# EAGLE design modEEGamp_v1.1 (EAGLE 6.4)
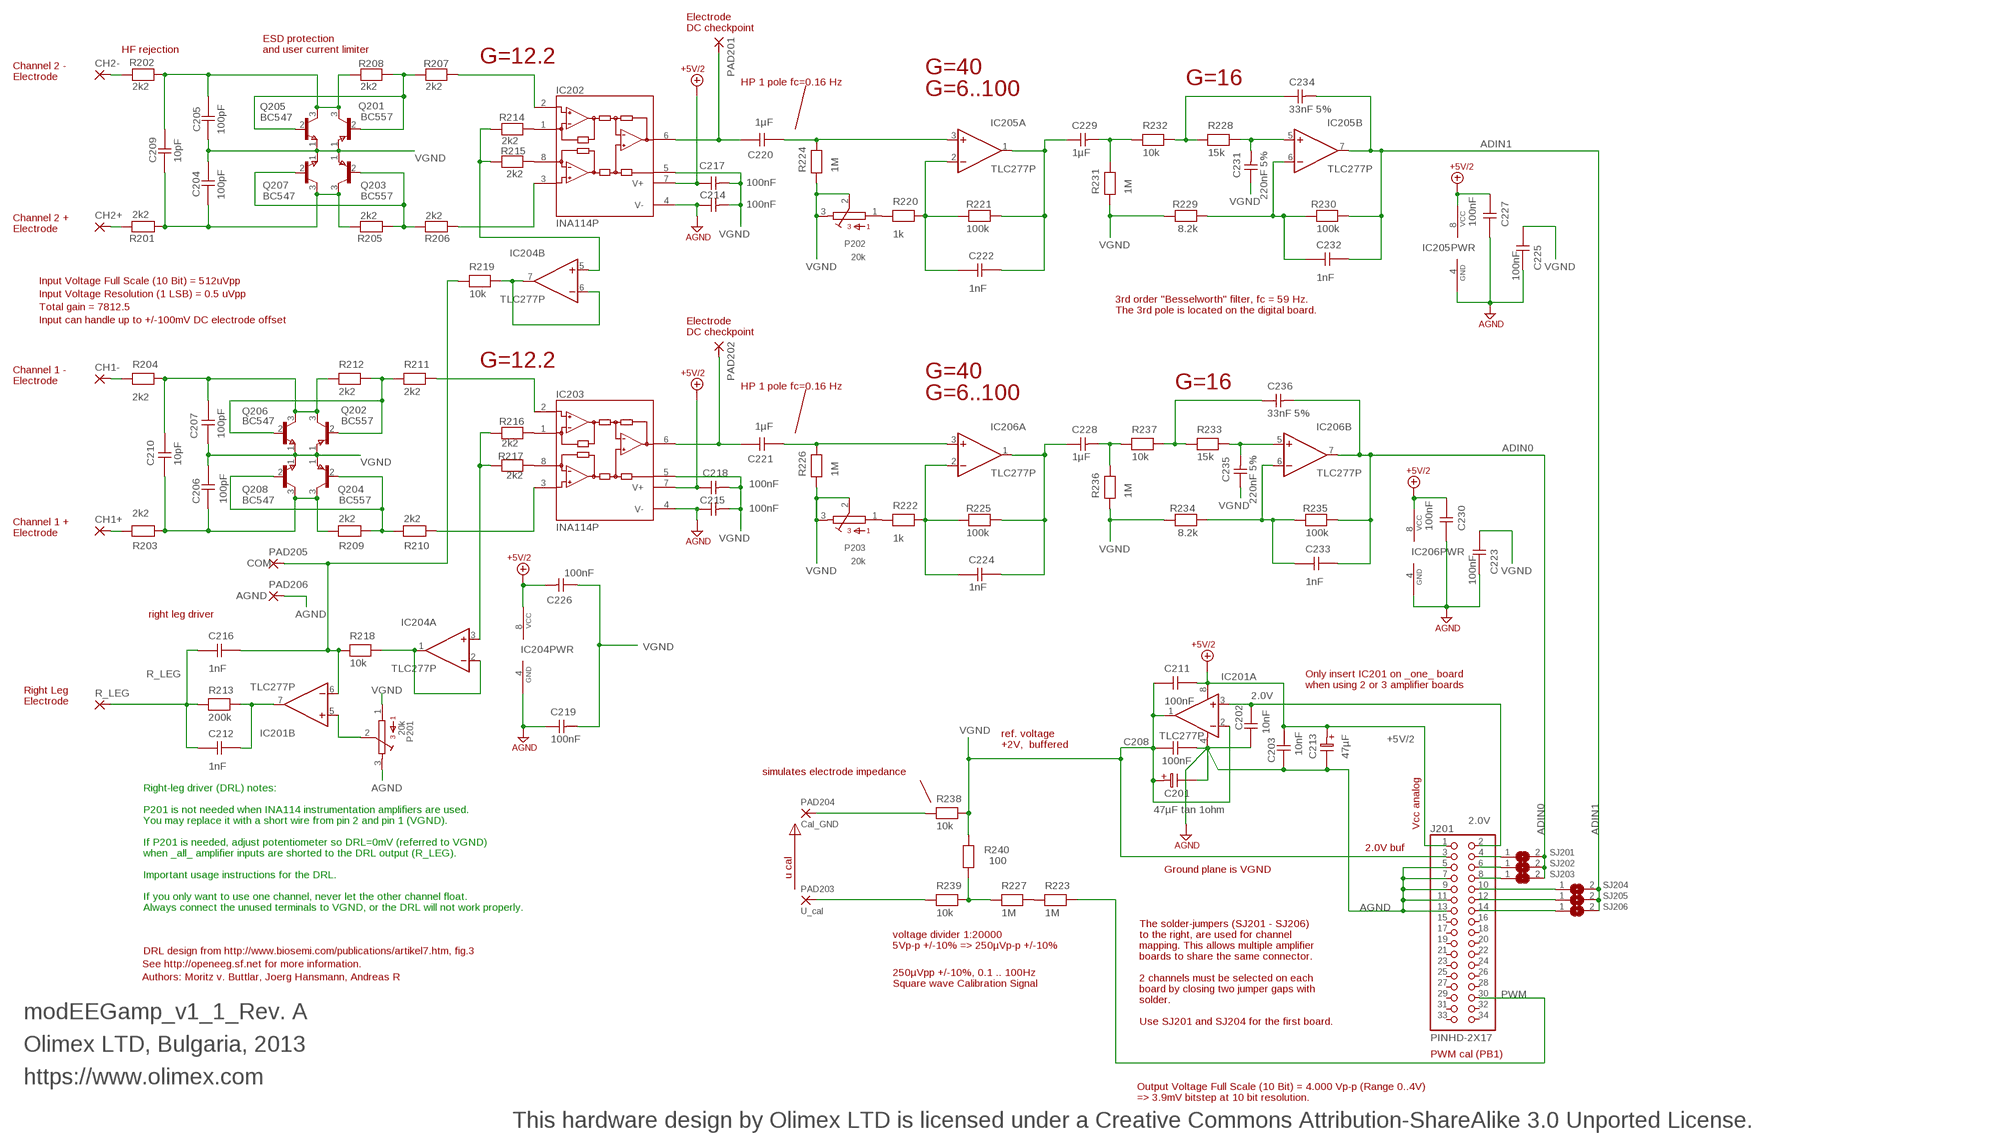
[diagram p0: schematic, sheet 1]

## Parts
C201  47µF tan 1ohm  ELC-2,5  [EL25B]
C202  10nF  CAPNP-5@2  [C-5]
C203  10nF  CAPNP-7,5  [C-5]
C204  100pF  CAPNP-7,5  [C-5]
C205  100pF  CAPNP-7,5  [C-5]
C206  100pF  CAPNP-7,5  [C-5]
C207  100pF  CAPNP-7,5  [C-5]
C208  100nF  CAPNP-7,5  [C-5]
C209  10pF  CAPNP-7,5  [C-5]
C210  10pF  CAPNP-7,5  [C-5]
C211  100nF  CAPNP-5@2  [C-5]
C212  1nF  CAPNP-7,5  [C-5]
C213  47µF  ELC-5  [EL25B]
C214  100nF  CAPNP-5  [C-5]
C215  100nF  CAPNP-5  [C-5]
C216  1nF  CAPNP-7,5  [C-5]
C217  100nF  CAPNP-5  [C-5]
C218  100nF  CAPNP-5  [C-5]
C219  100nF  CAPNP-5  [C-5]
C220  1µF  CAPNP-7,5@2  [C-10]
C221  1µF  CAPNP-7,5@2  [C-10]
C222  1nF  CAPNP-7,5  [C-5]
C223  100nF  CAPNP-5@2  [C-5]
C224  1nF  CAPNP-7,5  [C-5]
C225  100nF  CAPNP-5@2  [C-5]
C226  100nF  CAPNP-5  [C-5]
C227  100nF  CAPNP-5@2  [C-5]
C228  1µF  CAPNP-7,5@3  [C-10]
C229  1µF  CAPNP-7,5@3  [C-10]
C230  100nF  CAPNP-5@2  [C-5]
C231  220nF 5%  CAPNP-5  [C-5]
C232  1nF  CAPNP-7,5  [C-5]
C233  1nF  CAPNP-7,5  [C-5]
C234  33nF 5%  CAPNP-5  [C-5]
C235  220nF 5%  CAPNP-5  [C-5]
C236  33nF 5%  CAPNP-5  [C-5]
CH1+  1,6/0,8  [1,6/0,8]
CH1-  1,6/0,8  [1,6/0,8]
CH2+  1,6/0,8  [1,6/0,8]
CH2-  1,6/0,8  [1,6/0,8]
IC201  TLC277P  OPA2604AP  [DIL-08]
IC202  INA114P  [DIL-08]
IC203  INA114P  [DIL-08]
IC204  TLC277P  [DIL-08]
IC205  TLC277P  [DIL-08]
IC206  TLC277P  [DIL-08]
J201  PINHD-2X17  [2X17]
P201  20k  S64Y  [S64Y]
P202  20k  S64Y  [S64Y]
P203  20k  S64Y  [S64Y]
PAD201  1,6/0,8  [1,6/0,8]
PAD202  1,6/0,8  [1,6/0,8]
PAD203  U_cal  1,6/0,8  [WIREPAD1]
PAD204  Cal_GND  1,6/0,8  [WIREPAD1]
PAD205  COM  1,6/0,8  [1,6/0,8]
PAD206  AGND  1,6/0,8  [1,6/0,8]
Q201  BC557  [TO92]
Q202  BC557  [TO92]
Q203  BC557  [TO92]
Q204  BC557  [TO92]
Q205  BC547  [TO92]
Q206  BC547  [TO92]
Q207  BC547  [TO92]
Q208  BC547  [TO92]
R201  2k2  RESEU-10  [R-10]
R202  2k2  RESEU-10  [R-10]
R203  2k2  RESEU-10  [R-10]
R204  2k2  RESEU-10  [R-10]
R205  2k2  RESEU-10  [R-10]
R206  2k2  RESEU-10  [R-10]
R207  2k2  RESEU-10  [R-10]
R208  2k2  RESEU-10  [R-10]
R209  2k2  RESEU-10  [R-10]
R210  2k2  RESEU-10  [R-10]
R211  2k2  RESEU-10  [R-10]
R212  2k2  RESEU-10  [R-10]
R213  200k  RESEU-10  [R-10]
R214  2k2  RESEU-7,5  [R-10]
R215  2k2  RESEU-7,5  [R-10]
R216  2k2  RESEU-7,5  [R-10]
R217  2k2  RESEU-7,5  [R-10]
R218  10k  RESEU-10  [R-10]
R219  10k  RESEU-10@2  [R-10]
R220  1k  RESEU-7,5  [R-10]
R221  100k  RESEU-7,5  [R-10]
R222  1k  RESEU-7,5  [R-10]
R223  1M  RESEU-10@2  [R-10]
R224  1M  RESEU-7,5  [R-10]
R225  100k  RESEU-7,5  [R-10]
R226  1M  RESEU-7,5  [R-10]
R227  1M  RESEU-10@2  [R-10]
R228  15k  RESEU-7,5@2  [R-10]
R229  8.2k  RESEU-7,5  [R-10]
R230  100k  RESEU-7,5  [R-10]
R231  1M  RESEU-7,5  [R-10]
R232  10k  RESEU-7,5@2  [R-10]
R233  15k  RESEU-7,5@2  [R-10]
R234  8.2k  RESEU-7,5  [R-10]
R235  100k  RESEU-7,5  [R-10]
R236  1M  RESEU-7,5  [R-10]
R237  10k  RESEU-7,5@2  [R-10]
R238  10k  RESEU-7,5  [R-10]
R239  10k  RESEU-7,5  [R-10]
R240  100  RESEU-7,5  [R-10]
R_LEG  1,6/0,8  [1,6/0,8]
SJ201  SJ  [SJ5X5]
SJ202  SJ  [SJ5X5]
SJ203  SJ  [SJ5X5]
SJ204  SJ  [SJ5X5]
SJ205  SJ  [SJ5X5]
SJ206  SJ  [SJ5X5]

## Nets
2.0V: C202.1 IC201.3(A:+IN) J201.2
+5V/2: C203.1 C211.2 C213.1 C217.1 C218.1 C226.2 C227.2 C230.2 IC201.8(A:V+) IC202.7(V+) IC203.7(V+) IC204.8(PWR:VCC) IC205.8(PWR:VCC) IC206.8(PWR:VCC) J201.1
ADIN0: C233.2 C236.2 IC206.7(B:OUT) R235.2 SJ201.2 SJ202.2 SJ203.2
ADIN1: C232.2 C234.2 IC205.7(B:OUT) R230.2 SJ204.2 SJ205.2 SJ206.2
AGND: C201.2 C202.2 C203.2 C208.2 C213.2 C214.1 C215.1 C219.1 C223.1 C225.1 C227.1 C230.1 IC201.4(A:V-) IC202.4(V-) IC203.4(V-) IC204.4(PWR:GND) IC205.4(PWR:GND) IC206.4(PWR:GND) J201.5 J201.7 J201.9 J201.11 J201.13 P201.3 PAD206.1(P)
N$1: IC202.1(RG) R214.1
N$2: IC202.8(RG) R215.1
N$3: IC204.5(B:+IN) R214.2 R215.2
N$4: C220.2 IC202.6(OUT) PAD201.1(P)
N$5: IC202.2(-IN) R207.2
N$6: CH1-.1(P) R204.1
N$7: IC202.3(+IN) R206.2
N$8: Q201.2(B) Q205.2(B) R207.1 R208.2
N$9: C205.2 C209.2 Q201.3(C) Q205.3(C) R202.2 R208.1
N$10: Q203.2(B) Q207.2(B) R205.2 R206.1
N$11: CH1+.1(P) R203.1
N$12: IC204.3(A:+IN) R216.2 R217.2
N$13: C204.1 C209.1 Q203.3(C) Q207.3(C) R201.2 R205.1
N$14: IC203.1(RG) R216.1
N$15: CH2-.1(P) R202.1
N$16: CH2+.1(P) R201.1
N$17: C220.1 IC205.3(A:+IN) R224.2
N$18: C222.1 IC205.2(A:-IN) R220.2 R221.1
N$19: P202.1 R220.1
N$20: IC203.8(RG) R217.1
N$21: IC203.2(-IN) R211.2
N$22: C222.2 C229.1 IC205.1(A:OUT) R221.2
N$23: C229.2 R231.2 R232.1
N$24: C232.1 IC205.6(B:-IN) R229.2 R230.1
N$25: C221.2 IC203.6(OUT) PAD202.1(P)
N$26: J201.4 SJ201.1
N$27: IC203.3(+IN) R210.2
N$28: C221.1 IC206.3(A:+IN) R226.2
N$29: Q202.2(B) Q206.2(B) R211.1 R212.2
N$30: PAD204.1(P) R238.1
N$31: J201.6 SJ202.1
N$32: C207.2 C210.2 Q202.3(C) Q206.3(C) R204.2 R212.1
N$33: C212.2 IC201.7(B:OUT) R213.2
N$34: R227.1 R239.2 R240.2
N$35: J201.8 SJ203.1
N$36: J201.10 SJ204.1
N$37: J201.12 SJ205.1
N$38: C224.1 IC206.2(A:-IN) R222.2 R225.1
N$39: Q204.2(B) Q208.2(B) R209.2 R210.1
N$40: P203.1 R222.1
N$41: C216.2 IC201.6(B:-IN) PAD205.1(P) R218.1 R219.1
N$42: C224.2 C228.1 IC206.1(A:OUT) R225.2
N$43: C206.1 C210.1 Q204.3(C) Q208.3(C) R203.2 R209.1
N$44: J201.14 SJ206.1
N$45: IC204.6(B:-IN) IC204.7(B:OUT) R219.2
N$46: R223.1 R227.2
N$47: IC201.5(B:+IN) P201.2
N$48: PAD203.1(P) R239.1
N$49: C233.1 IC206.6(B:-IN) R234.2 R235.1
N$50: C228.2 R236.2 R237.1
N$51: C236.1 R233.1 R237.2
N$52: IC204.1(A:OUT) IC204.2(A:-IN) R218.2
N$53: C234.1 R228.1 R232.2
N$54: C231.2 IC205.5(B:+IN) R228.2
N$57: C235.2 IC206.5(B:+IN) R233.2
PWM: J201.30 R223.2
R_LEG: C212.1 C216.1 R213.1 R_LEG.1(P)
VGND: C201.1 C204.2 C205.1 C206.2 C207.1 C208.1 C211.1 C214.2 C215.2 C217.2 C218.2 C219.2 C223.2 C225.2 C226.1 C231.1 C235.1 IC201.1(A:OUT) IC201.2(A:-IN) IC202.5(REF) IC203.5(REF) J201.3 P201.1 P202.2 P202.3 P203.2 P203.3 Q201.1(E) Q202.1(E) Q203.1(E) Q204.1(E) Q205.1(E) Q206.1(E) Q207.1(E) Q208.1(E) R224.1 R226.1 R229.1 R231.1 R234.1 R236.1 R238.2 R240.1
Unconnected: J201.15 J201.16 J201.17 J201.18 J201.19 J201.20 J201.21 J201.22 J201.23 J201.24 J201.25 J201.26 J201.27 J201.28 J201.29 J201.31 J201.32 J201.33 J201.34

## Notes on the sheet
- Electrode
- DC checkpoint
- ESD protection
- HF rejection | and user current limiter
- G=12.2
- Channel 2 -
- G=40
- Electrode
- HP 1 pole fc=0.16 Hz | G=16
- G=6..100
- Channel 2 +
- Electrode
- Input Voltage Full Scale (10 Bit) = 512uVpp
- Input Voltage Resolution (1 LSB) = 0.5 uVpp
- 3rd order "Besselworth" filter, fc = 59 Hz.
- Total gain = 7812.5
- The 3rd pole is located on the digital board.
- Input can handle up to +/-100mV DC electrode offset | Electrode
- DC checkpoint
- G=12.2
- Channel 1 -
- G=40
- Electrode
- HP 1 pole fc=0.16 Hz | G=16
- G=6..100
- Channel 1 +
- Electrode
- right leg driver
- Only insert IC201 on _one_ board
- when using 2 or 3 amplifier boards
- Right Leg
- Electrode
- ref. voltage
- +2V,  buffered
- simulates electrode impedance
- Right-leg driver (DRL) notes:
- P201 is not needed when INA114 instrumentation amplifiers are used.
- You may replace it with a short wire from pin 2 and pin 1 (VGND).
- Vcc analog
- If P201 is needed, adjust potentiometer so DRL=0mV (referred to VGND)
- 2.0V buf
- when _all_ amplifier inputs are shorted to the DRL output (R_LEG). | u cal
- Ground plane is VGND
- Important usage instructions for the DRL.
- If you only want to use one channel, never let the other channel float.
- Always connect the unused terminals to VGND, or the DRL will not work properly.
- The solder-jumpers (SJ201 - SJ206)
- voltage divider 1:20000 | to the right, are used for channel
- 5Vp-p +/-10% => 250µVp-p +/-10% | mapping. This allows multiple amplifier
- DRL design from http://www.biosemi.com/publications/artikel7.htm, fig.3
- boards to share the same connector.
- See http://openeeg.sf.net for more information.
- 250µVpp +/-10%, 0.1 .. 100Hz
- Authors: Moritz v. Buttlar, Joerg Hansmann, Andreas R | 2 channels must be selected on each
- Square wave Calibration Signal
- board by closing two jumper gaps with
- solder.
- modEEGamp_v1_1_Rev. A
- Use SJ201 and SJ204 for the first board.
- Olimex LTD, Bulgaria, 2013
- PWM cal (PB1)
- https://www.olimex.com
- Output Voltage Full Scale (10 Bit) = 4.000 Vp-p (Range 0..4V)
- => 3.9mV bitstep at 10 bit resolution.
- This hardware design by Olimex LTD is licensed under a Creative Commons Attribution-ShareAlike 3.0 Unported License.

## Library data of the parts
C201 = DISCRETE@3:ELC-2,5
C202 C211 C223 C225 C227 C230 = DISCRETE:CAPNP-5@2
C203-C210 C212 C216 C222 C224 C232 C233 = DISCRETE:CAPNP-7,5
C213 = DISCRETE@2:ELC-5
C214 C215 C217-C219 C226 C231 C234-C236 = DISCRETE:CAPNP-5
C220 C221 = DISCRETE:CAPNP-7,5@2
C228 C229 = DISCRETE:CAPNP-7,5@3
CH1+ CH1- CH2+ CH2- PAD201 PAD202 PAD205 PAD206 R_LEG = WIREPAD:1,6/0,8: THROUGH-HOLE PAD
IC201 = BURR:OPA2604AP
IC202 IC203 = BURR:INA114P
IC204-IC206 = BURR:TLC277P
J201 = pinhead_:PINHD-2X17
P201 = TRIMPOT:S64Y
P202 P203 = TRIMPOT@2:S64Y
PAD203 PAD204 = WIREPAD@2:1,6/0,8
Q201-Q204 = pnp:BC557
Q205-Q208 = NPN:BC547
R201-R213 R218 = DISCRETE:RESEU-10
R214-R217 R220-R222 R224-R226 R229-R231 R234-R236 R238-R240 = DISCRETE:RESEU-7,5
R219 R223 R227 = DISCRETE:RESEU-10@2
R228 R232 R233 R237 = DISCRETE:RESEU-7,5@2
SJ201-SJ206 = JUMPER:SJ

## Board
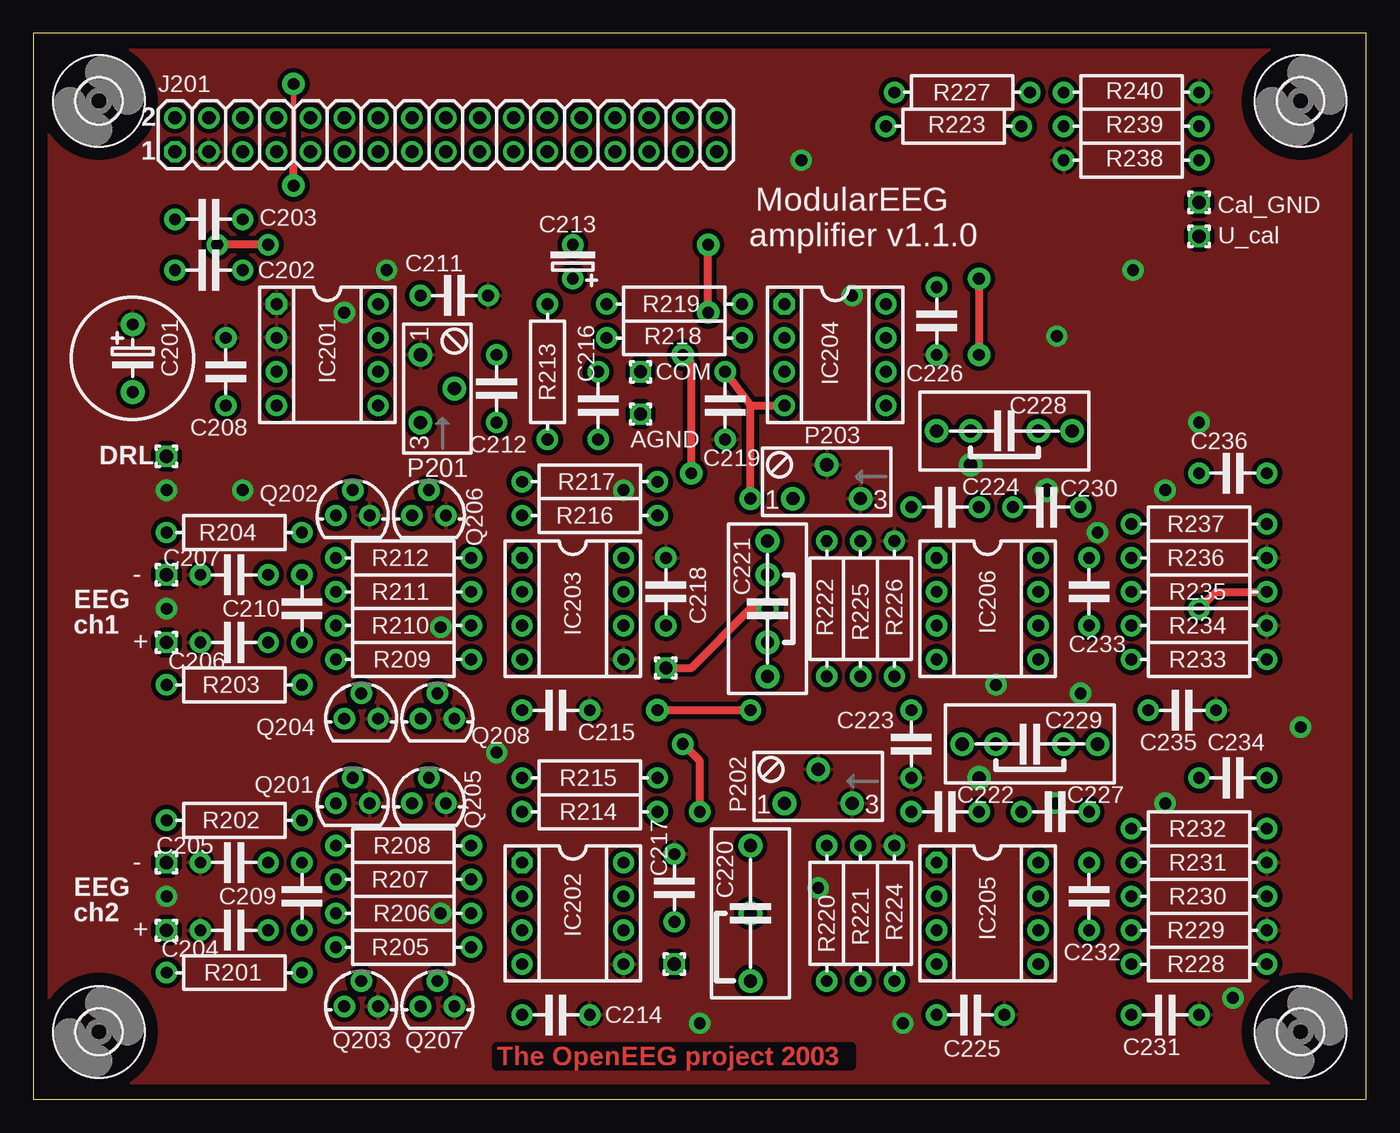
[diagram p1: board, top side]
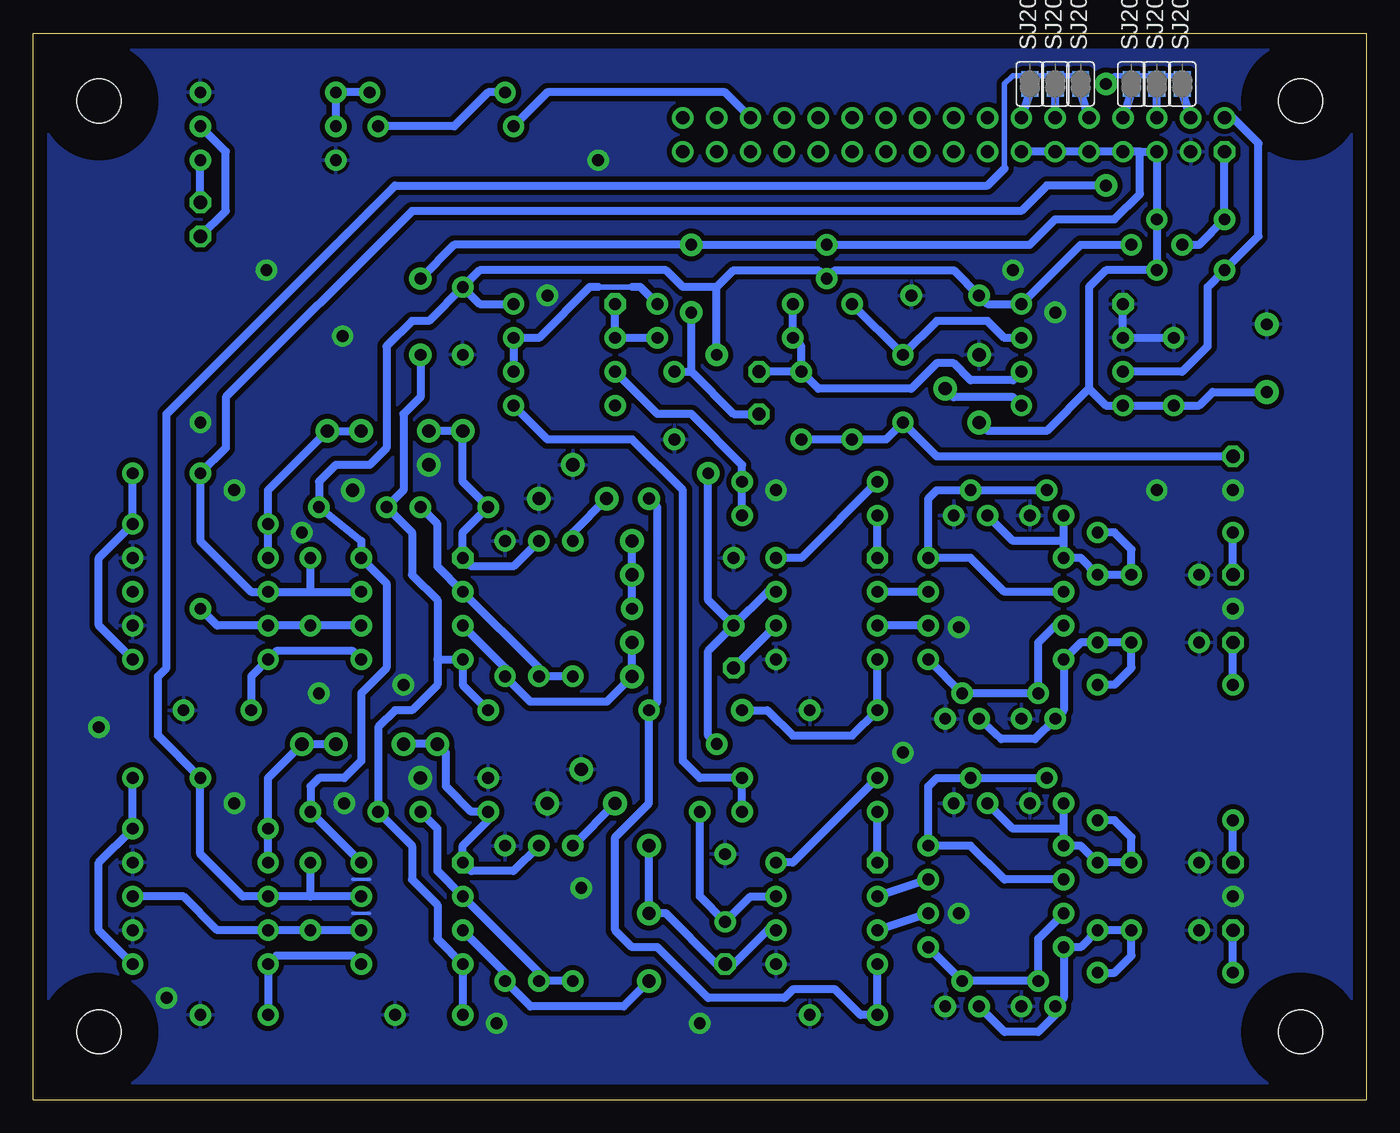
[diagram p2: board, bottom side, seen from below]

Size 100 x 80.01 mm. Coordinates in mm from the lower left corner, seen from the top.
Outline: 100,0.01 100,80.01 0,80.01 0,0.01
Outline: 100,0 0,0
Copper layers used: Top, Bottom

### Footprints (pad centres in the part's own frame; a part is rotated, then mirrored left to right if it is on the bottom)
ES-5 = drill 0.889 pad 1.778 round: 1 -2.54,0; 2 2.54,0
C-5 = drill 0.889 pad 1.6 round: 1 -2.54,0; 2 2.54,0
EL25B = drill 0.889 pad 1.6 round: 1 -1.27,0; 2 1.27,0
C-10 = drill 0.991 pad 1.778 round: 1 -5.08,0; 2 5.08,0
WIREPAD1 = drill 0.991 pad 1.6 octagon: 1 0,0
DIL-08 = drill 0.889 pad 1.6 octagon: 1 -3.81,-3.81 | drill 0.889 pad 1.6 round: 2 -1.27,-3.81; 3 1.27,-3.81; 4 3.81,-3.81; 5 3.81,3.81; 6 1.27,3.81; 7 -1.27,3.81; 8 -3.81,3.81
2X17 = drill 0.991 pad 1.6 octagon: 1 -20.32,-1.27 | drill 0.991 pad 1.6 round: 2 -20.32,1.27; 3 -17.78,-1.27; 4 -17.78,1.27; 5 -15.24,-1.27; 6 -15.24,1.27; 7 -12.7,-1.27; 8 -12.7,1.27; 9 -10.16,-1.27; 10 -10.16,1.27; 11 -7.62,-1.27; 12 -7.62,1.27; 13 -5.08,-1.27; 14 -5.08,1.27; 15 -2.54,-1.27; 16 -2.54,1.27; 17 0,-1.27; 18 0,1.27; 19 2.54,-1.27; 20 2.54,1.27; 21 5.08,-1.27; 22 5.08,1.27; 23 7.62,-1.27; 24 7.62,1.27; 25 10.16,-1.27; 26 10.16,1.27; 27 12.7,-1.27; 28 12.7,1.27; 29 15.24,-1.27; 30 15.24,1.27; 31 17.78,-1.27; 32 17.78,1.27; 33 20.32,-1.27; 34 20.32,1.27
S64Y = drill 0.991 pad 1.778 round: 1 2.54,1.27; 2 0,-1.27; 3 -2.54,1.27
TO92 = drill 0.889 pad 1.6 round: 1 1.27,0; 2 0,1.905; 3 -1.27,0
R-10 = drill 0.889 pad 1.6 round: 1 -5.08,0; 2 5.08,0
SJ5X5 = smd 0.635 x 1.27: 1 -0.635,0; 2 0.635,0
3,3 = hole 3.3: 0,0

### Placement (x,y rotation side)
C201  47µF tan 1ohm  [ES-5]  7.46,55.64 270 top
C202  13.17,62.24 0 top
C203  13.17,66.05 0 top
C204  15.08,12.71 180 top
C205  15.08,17.79 0 top
C206  15.08,34.3 180 top
C207  15.08,39.38 0 top
C208  14.44,54.62 270 top
C209  20.15,15.25 90 top
C210  20.15,36.84 90 top
C211  31.58,60.34 180 top
C212  34.76,53.35 90 top
C213  40.48,62.88 90 top
C214  39.2,6.36 0 top
C215  39.2,29.22 0 top
C216  42.38,52.08 90 top
C217  48.09,15.88 90 top
C218  47.46,38.11 90 top
C219  51.91,52.08 270 top
C220  53.81,13.98 90 top
C221  55.08,36.84 90 top
C222  68.41,21.6 180 top
C223  65.88,26.68 270 top
C224  68.41,44.46 180 top
C225  70.32,6.36 0 top
C226  67.78,58.43 90 top
C227  76.67,21.6 0 top
C228  72.86,50.17 0 top
C229  74.77,26.68 0 top
C230  76.03,44.46 0 top
C231  84.92,6.36 180 top
C232  79.21,15.25 90 top
C233  79.21,38.11 90 top
C234  90,24.14 180 top
C235  86.19,29.22 180 top
C236  90,47 180 top
CH1+  [WIREPAD1]  10,34.3 90 top
CH1-  [WIREPAD1]  10,39.38 90 top
CH2+  [WIREPAD1]  10,12.71 0 top
CH2-  [WIREPAD1]  10,17.79 0 top
IC201  22.06,55.89 270 top
IC202  40.48,13.98 270 top
IC203  40.48,36.84 270 top
IC204  60.16,55.89 270 top
IC205  71.59,13.98 270 top
IC206  71.59,36.84 270 top
J201  30.95,72.4 0 top
P201  30.31,53.35 90 top
P202  58.89,23.51 180 top
P203  59.52,46.36 180 top
PAD201  [WIREPAD1]  48.09,10.17 270 top
PAD202  [WIREPAD1]  47.46,32.39 270 top
PAD203  87.47,64.78 0 top
PAD204  87.47,67.32 0 top
PAD205  COM  [WIREPAD1]  45.55,54.62 0 top
PAD206  AGND  [WIREPAD1]  45.55,51.45 0 top
Q201  23.96,22.24 0 top
Q202  23.96,43.82 0 top
Q203  24.6,7 0 top
Q204  24.6,28.59 0 top
Q205  29.68,22.24 0 top
Q206  29.68,43.82 0 top
Q207  30.31,7 0 top
Q208  30.31,28.59 0 top
R201  15.08,9.54 0 top
R202  15.08,20.96 0 top
R203  15.08,31.12 0 top
R204  15.08,42.55 0 top
R205  27.77,11.44 0 top
R206  27.77,13.98 0 top
R207  27.77,16.52 0 top
R208  27.77,19.06 0 top
R209  27.77,33.03 0 top
R210  27.77,35.57 0 top
R211  27.77,38.11 0 top
R212  27.77,40.65 0 top
R213  38.57,54.62 90 top
R214  41.74,21.6 0 top
R215  41.74,24.14 0 top
R216  41.74,43.82 0 top
R217  41.74,46.36 0 top
R218  48.09,57.16 0 top
R219  48.09,59.7 0 top
R220  59.52,13.98 270 top
R221  62.06,13.98 90 top
R222  59.52,36.84 270 top
R223  69.05,73.04 180 top
R224  64.61,13.98 270 top
R225  62.06,36.84 90 top
R226  64.61,36.84 270 top
R227  69.69,75.58 180 top
R228  87.47,10.17 180 top
R229  87.47,12.71 180 top
R230  87.47,15.25 180 top
R231  87.47,17.79 180 top
R232  87.47,20.33 0 top
R233  87.47,33.03 180 top
R234  87.47,35.57 180 top
R235  87.47,38.11 180 top
R236  87.47,40.65 180 top
R237  87.47,43.19 0 top
R238  82.39,70.5 180 top
R239  82.39,73.04 180 top
R240  82.39,75.58 180 top
R_LEG  [WIREPAD1]  10,48.27 0 top
SJ201  13.81,76.21 90 bottom
SJ202  15.71,76.21 90 bottom
SJ203  17.61,76.21 90 bottom
SJ204  21.42,76.21 90 bottom
SJ205  23.33,76.21 90 bottom
SJ206  25.23,76.21 90 bottom
U$10  [3,3]  95.08,74.94 0 top
U$11  [3,3]  4.92,5.09 0 top
U$12  [3,3]  95.08,5.09 0 top
U$13  [3,3]  4.92,74.94 0 top

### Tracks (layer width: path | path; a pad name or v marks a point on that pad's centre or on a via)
2.0V
  Bottom 0.61: J201.2 10,73.67 8.09,71.77 8.09,64.78 C202.1 11.9,60.97 11.9,56.52 13.81,54.62 IC201.3
+5V/2  (via drill 0.89 pad 1.6, 0.89 pad 1.68)
  Top 0.61: v17.61,64.15 v13.81,64.15 | v49.37,47 49.37,55.25 v48.73,55.89 | v50,21.6 50,25.41 v48.73,26.68
  Bottom 0.61: IC202.7 46.19,15.25 C217.1 50,15.25 v50,21.6 | C218.1 49.37,33.66 49.37,27.32 v48.73,26.68 | IC203.7 44.92,38.11 C218.1 | C218.1 49.37,37.48 v49.37,47 | IC205.8 C227.2 79.21,23.51 78.58,24.14 76.67,24.14 75.4,25.41 75.4,30.49 73.5,32.39 73.5,38.74 IC206.8 75.4,41.92 C230.2 78.58,46.36 77.3,47.63 74.77,47.63 73.5,48.91 73.5,56.52 71.59,58.43 70.32,58.43 C226.2 | C226.2 66.51,62.24 52.54,62.24 51.27,60.97 48.73,60.97 | C226.2 66.51,59.7 IC204.8 | 48.73,60.97 47.46,62.24 41.11,62.24 C213.1 39.84,62.24 30.95,62.24 C211.2 28.41,59.7 IC201.8 21.42,64.15 v17.61,64.15 | J201.1 C203.1 12.54,64.15 v13.81,64.15 | v48.73,55.89 48.73,60.97
ADIN0  (via drill 0.89 pad 1.68)
  Top 0.406: 19.52,69.86 v19.52,76.21
  Top 0.61: v19.52,68.59 19.52,69.86
  Bottom 0.406: v19.52,76.21 18.88,76.84 SJ203.2 SJ202.2 SJ201.2
  Bottom 0.61: v19.52,68.59 23.96,68.59 25.87,66.69 71.59,66.69 85.56,52.71 85.56,48.91 C236.2 87.47,41.92 83.66,38.11 R235.2 79.21,38.11 | 79.21,38.11 IC206.7 | 79.21,38.11 C233.2
ADIN1
  Bottom 0.406: 27.14,69.86 27.14,76.21 26.5,76.84 SJ206.2 SJ205.2 SJ204.2
  Bottom 0.61: 27.14,69.86 28.41,68.59 72.86,68.59 90,51.45 90,32.39 90.64,31.76 90.64,27.32 C234.2 87.47,18.43 84.29,15.25 R230.2 79.21,15.25 | IC205.7 79.21,15.25 | 79.21,15.25 C232.2
AGND  (via drill 0.89 pad 1.6, 0.89 pad 1.68)
  Top 0.61: v53.81,29.22 v46.82,29.22 | v70.95,61.6 v70.95,55.89 | v53.81,45.09 53.81,52.08 | 53.81,52.08 IC204.4 | 53.81,52.08 C219.1 | v50.63,59.06 v50.63,64.15
  Bottom 0.61: IC203.4 C215.1 38.57,27.32 43.02,27.32 44.92,29.22 v46.82,29.22 | IC202.4 C214.1 37.94,6.36 39.84,8.27 43.02,8.27 43.65,7.63 49.37,7.63 53.17,11.44 55.08,11.44 56.35,12.71 56.35,19.7 53.81,22.24 v53.81,29.22 53.17,29.86 53.17,44.46 v53.81,45.09 | C225.1 IC205.4 69.69,12.07 69.69,14.62 71.59,16.52 71.59,19.06 C227.1 74.13,27.95 72.86,29.22 71.59,29.22 69.69,31.12 69.69,33.03 | 69.69,33.03 69.69,37.48 71.59,39.38 71.59,42.55 C230.1 72.22,45.73 72.22,51.45 70.95,52.71 v70.95,55.89 | 69.69,33.03 IC206.4 67.78,31.12 C223.1 | 16.98,71.13 J201.5 C203.2 C202.2 19.52,62.24 20.79,60.97 20.79,53.35 | 16.98,71.13 J201.7 J201.9 J201.11 J201.13 | v70.95,61.6 68.41,64.15 v50.63,64.15 C213.2 25.23,64.15 23.33,66.05 18.88,66.05 16.98,67.95 16.98,71.13 | C219.1 50.63,54.62 | 50.63,54.62 v50.63,59.06 | C201.2 11.52,53.1 12.54,52.08 C208.2 IC201.4 19.52,52.08 20.79,53.35 | P201.3 28.41,50.17 23.96,50.17 20.79,53.35 | PAD206.1 47.46,51.45 50.63,54.62
N$1
  Bottom 0.61: IC202.1 R214.1
N$2
  Bottom 0.61: IC202.8 43.02,17.79 R215.1
N$3
  Bottom 0.61: R214.2 R215.2 50,24.14 51.27,25.41 51.27,45.73 55.08,49.54 61.43,49.54 IC204.5
N$4  (via drill 0.99 pad 1.78)
  Bottom 0.61: IC202.6 44.92,12.71 47.46,10.17 PAD201.1 48.73,10.17 52.54,13.98 v53.81,13.98 C220.2
N$5
  Bottom 0.61: R207.2 IC202.2
N$6
  Bottom 0.61: CH1-.1 R204.1
N$7
  Bottom 0.61: R206.2 IC202.3
N$8
  Bottom 0.61: R207.1 27.14,16.52 29.68,19.06 R208.2 32.85,23.51 32.22,24.14 Q205.2 Q201.2
N$9
  Bottom 0.61: R202.2 18.88,20.96 17.61,19.7 C205.2 C209.2 21.42,19.06 R208.1 22.7,20.33 | 22.7,20.33 Q201.3 | Q205.3 26.5,20.33 22.7,20.33
N$10
  Bottom 0.61: R206.1 24.6,12.07 Q203.2 Q207.2 R205.2
N$11
  Bottom 0.61: R203.1 CH1+.1
N$12
  Bottom 0.61: R216.2 R217.2 46.82,47.63 50.63,51.45 53.17,51.45 IC204.3
N$13
  Bottom 0.61: R201.2 18.88,9.54 17.61,10.8 C204.1 C209.1 21.42,11.44 R205.1 22.7,7.63 Q203.3 23.33,6.36 24.6,5.09 27.14,5.09 Q207.3
N$14
  Bottom 0.61: IC203.1 R216.1
N$15
  Bottom 0.61: CH2-.1 R202.1
N$16
  Bottom 0.61: R201.1 CH2+.1
N$17
  Bottom 0.61: C220.1 55.71,7 62.7,7 R224.2 64.61,9.54 IC205.3
N$18
  Bottom 0.61: R220.2 R221.1 62.06,9.54 IC205.2 69.69,17.16 69.69,20.33 C222.1
N$19
  Bottom 0.61: P202.1 R220.1
N$20
  Bottom 0.61: R217.1 42.38,40.65 IC203.8
N$21
  Bottom 0.61: R211.2 IC203.2
N$22  (via drill 0.99 pad 1.78)
  Bottom 0.61: R221.2 63.97,17.16 67.14,17.16 IC205.1 67.78,19.06 65.88,20.96 C222.2 67.14,21.6 69.05,23.51 69.05,26.05 C229.1 v72.22,26.68
N$23  (via drill 0.99 pad 1.78)
  Bottom 0.61: R231.2 R232.1 82.39,24.14 C229.2 v77.3,26.68
N$24
  Bottom 0.61: IC205.6 C232.1 R229.2 86.19,12.71 88.73,15.25 R230.1
N$25  (via drill 0.89 pad 1.68, 0.99 pad 1.78)
  Top 0.61: PAD202.1 49.37,32.39 53.81,36.84 v55.08,36.84
  Bottom 0.61: PAD202.1 IC203.6 | v55.08,36.84 v55.08,39.38 C221.2
N$26
  Bottom 0.61: J201.4 SJ201.1
N$27
  Bottom 0.61: R210.2 IC203.3
N$28  (via drill 0.99 pad 1.78)
  Bottom 0.61: v55.08,34.3 C221.1 56.98,29.86 62.7,29.86 R226.2 64.61,32.39 IC206.3
N$29
  Bottom 0.61: R211.1 27.14,38.11 29.68,40.65 R212.2 32.85,45.09 32.22,45.73 Q206.2 Q202.2
N$30
  Bottom 0.61: PAD204.1 R238.1
N$31
  Bottom 0.61: J201.6 SJ202.1
N$32
  Bottom 0.61: 22.7,41.92 R212.1 21.42,40.65 C210.2 C207.2 17.61,41.28 18.88,42.55 R204.2 | 22.7,41.92 26.5,41.92 Q206.3 | 22.7,41.92 Q202.3
N$33
  Bottom 0.61: IC201.7 27.14,57.16 28.41,58.43 32.22,58.43 C212.2 R213.2
N$34
  Bottom 0.61: R239.2 R240.2 R227.1
N$35
  Bottom 0.61: SJ203.1 J201.8
N$36
  Bottom 0.61: J201.10 SJ204.1
N$37
  Bottom 0.61: J201.12 SJ205.1
N$38
  Bottom 0.61: R222.2 R225.1 62.06,32.39 IC206.2 69.69,40.02 69.69,43.19 C224.1
N$39
  Bottom 0.61: R210.1 23.33,35.57 24.6,34.3 Q204.2 Q208.2 R209.2
N$40
  Bottom 0.61: P203.1 59.52,42.55 R222.1
N$41
  Bottom 0.61: R219.1 R218.1 42.38,56.52 C216.2 | C216.2 41.11,53.35 34.12,53.35 32.22,55.25 30.95,55.25 29.68,53.98 26.5,53.98 IC201.6 | C216.2 PAD205.1
N$42  (via drill 0.99 pad 1.78)
  Bottom 0.61: v70.32,50.17 C228.1 67.78,46.36 C224.2 67.78,42.55 IC206.1 67.14,40.02 63.97,40.02 R225.2
N$43
  Bottom 0.61: R203.2 18.88,31.12 17.61,32.39 C206.1 C210.1 21.42,34.3 R209.1 22.7,29.22 Q204.3 24.85,27.06 27.39,27.06 Q208.3
N$44
  Bottom 0.61: SJ206.1 J201.14
N$45
  Bottom 0.406: 55.08,60.97 57.62,60.97
  Bottom 0.61: IC204.6 IC204.7 62.06,57.16 58.25,60.97 57.62,60.97 | R219.2 54.45,60.97 55.08,60.97
N$46
  Bottom 0.61: R227.2 65.88,75.58 68.41,73.04 R223.1
N$47
  Bottom 0.61: IC201.5 26.5,52.71 30.95,52.71 P201.2
N$48
  Bottom 0.61: R239.1 85.56,71.13 85.56,66.69 PAD203.1
N$49  (via drill 0.89 pad 1.6)
  Top 0.61: v87.47,36.84 88.73,38.11 R235.1
  Bottom 0.61: IC206.6 C233.1 R234.2 86.19,35.57 v87.47,36.84
N$50  (via drill 0.99 pad 1.78)
  Bottom 0.61: v75.4,50.17 C228.2 82.39,45.73 R237.1 R236.2
N$51
  Bottom 0.61: R233.1 95.08,35.57 95.08,40.65 R237.2 C236.1
N$52
  Bottom 0.61: IC204.1 IC204.2 R218.2
N$53
  Bottom 0.61: R228.1 95.08,12.71 95.08,17.79 R232.2 C234.1
N$54
  Bottom 0.61: IC205.5 76.03,10.8 81.75,10.8 R228.2 C231.2
N$57
  Bottom 0.61: IC206.5 76.03,33.66 81.75,33.66 R233.2 83.66,31.76 C235.2
PWM
  Bottom 0.61: J201.30 48.09,75.58 61.43,75.58 R223.2
R_LEG
  Bottom 0.61: C216.1 R213.1 36.03,49.54 C212.1 32.22,48.27 R_LEG.1
VGND  (via drill 0.89 pad 1.6, 0.99 pad 1.78)
  Bottom 0.254: 76.03,16.52 74.77,16.52 | 74.77,13.98 76.03,13.98
  Bottom 0.61: IC201.1 IC201.2 C208.1
  other vias: 30.57,35.44 30.57,13.98 26.5,62.24 15.71,45.73 44.28,45.73 34.76,26.05 10,36.84 10,15.25 10,45.73 50,5.72 65.24,5.72 58.89,15.88 23.33,59.06 57.62,70.5 78.58,30.49 84.92,45.73 84.92,22.24 87.47,50.81 76.8,57.29 82.51,62.24 72.22,31.12 79.84,42.55 76.03,45.73 70.32,47.63 61.43,60.34 76.67,22.24 70.95,24.14 95.08,27.95 90,7.63
  pour Top (isolate 0.356): 1.1,1.28 1.1,78.75 98.89,78.75 98.89,1.28
  pour Bottom (isolate 0.381): 1.1,78.75 98.89,78.75 98.89,1.28 1.1,1.28

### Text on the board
Top: The OpenEEG project 2003
tNames: 2 | 1 | ModularEEG | amplifier v1.1.0 | DRL | - | EEG | ch1 | + | - | EEG | ch2 | +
